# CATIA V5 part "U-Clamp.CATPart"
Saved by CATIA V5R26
Part number: U-Clamp
Bounding box of the stored display mesh (mm): x -22.987 to 22.987, y -6.35 to 6.35, z -25.4 to 28.702
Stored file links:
  D:\_Deepak\CATIA\CATIA V5 2015 Parts Files\EXE Files\Exercises\c13_catia_v5_6r2015_exr\C13Exr01_cat_v5-6r2015\U-Clamp_cat_v5-6r2015.CATPart
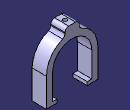
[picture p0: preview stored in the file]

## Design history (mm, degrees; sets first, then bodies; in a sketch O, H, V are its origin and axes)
Body1 (main body)
  Sketch1 on zx-plane, origin (0, 0, 0), H (-1, 0, 0), V (0, 0, 1)
    arc A1 centre (0, 0) radius 17.526 from (17.526, 0) to (-17.526, 0) ccw
    point P1 (-17.526, 0)
    point P2 (17.526, 0)
    line L1 (-17.526, 0) -> (-17.526, -22.352)
    point P3 (-17.526, -22.352)
    line L2 (-17.526, -22.352) -> (-13.462, -22.352)
    point P4 (-13.462, -22.352)
    line L3 (-13.462, -22.352) -> (-13.462, -25.4)
    point P5 (-13.462, -25.4)
    line L4 (-13.462, -25.4) -> (-22.987, -25.4)
    point P6 (-22.987, -25.4)
    line L5 (-22.987, -25.4) -> (-22.987, 0)
    point P7 (-22.987, 0)
    arc A2 centre (0, 0) radius 22.987 from (-22.987, 0) to (-6.35, 22.0925) cw
    point P9 (22.987, 0)
    point P10 (22.987, 0)
    point P11 (22.987, -25.4)
    line L6 (22.987, -25.4) -> (22.987, 0)
    point P12 (13.462, -25.4)
    line L7 (13.462, -25.4) -> (22.987, -25.4)
    point P13 (13.462, -22.352)
    line L8 (13.462, -22.352) -> (13.462, -25.4)
    point P14 (17.526, -22.352)
    line L9 (17.526, -22.352) -> (13.462, -22.352)
    point P15 (17.526, 0)
    line L10 (17.526, 0) -> (17.526, -22.352)
    line L11 (-6.35, 22.0925) -> (-6.35, 28.702)
    point P16 (-6.35, 28.702)
    line L12 (-6.35, 28.702) -> (6.35, 28.702)
    point P17 (6.35, 28.702)
    line L13 (6.35, 28.702) -> (6.35, 22.0925)
    point P18 (6.35, 22.0925)
    arc A3 centre (0, 0) radius 22.987 from (6.35, 22.0925) to (22.987, 0) cw
    radius A1 = 17.526
    distance L3 V = 13.462
    distance H L2 = 22.352
    distance H L4 = 25.4
    distance V L5 = 22.987
    distance P16 P17 = 12.7
    distance L11 V = 6.35
    distance L12 H = 28.702
    coincidence: P1 H, P2 H, P7 H, A2 P18, A2 A3, P2 P15, P9 P10
    tangency: L1 A1, A2 L5
    horizontal: L2 H, L4 H, L12 H
    vertical: L3 V, L5 V, L11 V, L13 V
    concentricity: A2 A1
    symmetry: P7 P10 V, P6 P11 V, L5 L6 V, P5 P12 V, L4 L7 V, P4 P13 V, L3 L8 V, P3 P14 V, L2 L9 V, P1 P15 V, L1 L10 V
  Pad1: profile Sketch1, direction (0, -1, 0), length 6.35, mirrored extent
  Fillet1: radius 3.302, on 4 edges
  Sketch2 on face of Pad1, origin (-0.057, 2.6412, 28.702), H (1, 0, 0), V (0, 1, 0)
    point P1 (0.057, -2.6412)
    reference intersected line E1 through (0.057, 0) direction (0, 1) from yz-plane
    reference intersected line E2 through (0, -2.6412) direction (-1, 0) from zx-plane
    coincidence: E1 P1, E2 P1
  Hole1: placed by Sketch2, at (0, 0, 28.702) direction (0, 0, -1), diameter 3.81, depth 25.4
